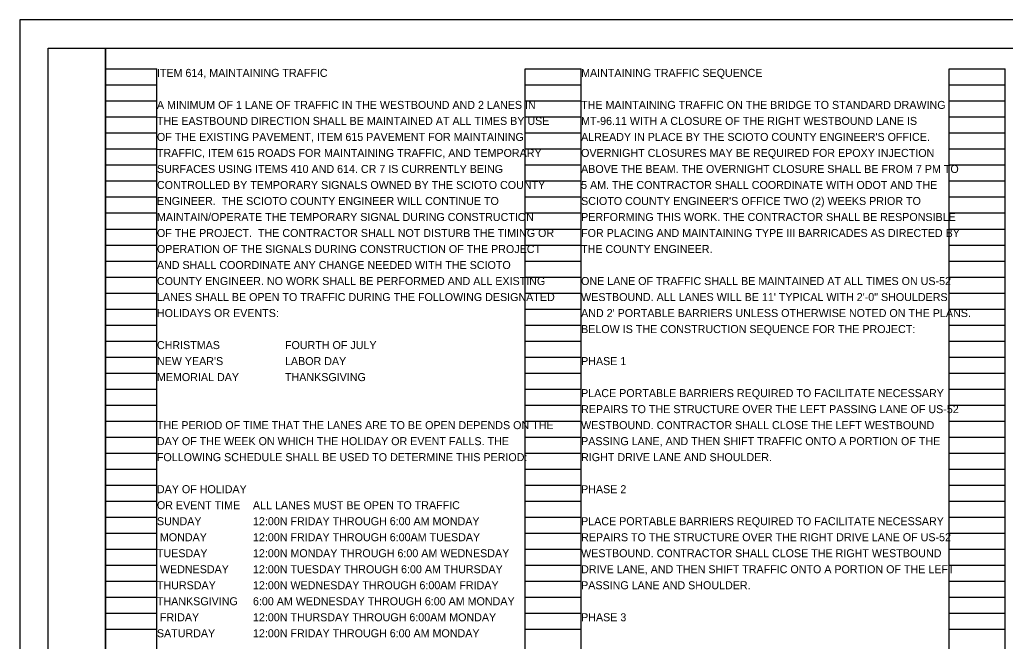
# Model space of a CAD drawing. Extents: x -36 to 68, y -39 to 86.
# Drawn here: x 0 to 17.24, y 11.13 to 22 of the extents above; entities that cross this region are included whole.
import ezdxf

# ---------------------------------------------------------------- set-up
doc = ezdxf.new("R2010")
doc.units = 0
for name, color, linetype in [('SH_Border', 7, 'Continuous'), ('SH_Cut_Line', 7, 'Continuous'), ('SH_Data', 7, 'Continuous'), ('SH_Text', 7, 'Continuous')]:
    doc.layers.add(name, color=color, linetype=linetype)

msp = doc.modelspace()

# ---------------------------------------------------------------- linework, layer by layer
at = {"layer": 'SH_Border'}
for points in [[(0.5, 21.5), (1.5, 21.5), (1.5, 0.5), (0.5, 0.5)], [(1.5, 21.5), (33.5, 21.5), (33.5, 0.5), (1.5, 0.5)]]:
    msp.add_lwpolyline(points, close=True, dxfattribs=at)
at = {"layer": 'SH_Cut_Line'}
msp.add_lwpolyline([(0, 0), (34, 0), (34, 22), (0, 22)], close=True, dxfattribs=at)
at = {"layer": 'SH_Data'}
for p, q in [((1.5, 0.98), (1.5, 21.14)), ((1.5, 21.14), (2.4, 21.14)), ((2.4, 0.98), (2.4, 21.14)), ((8.84, 0.98), (8.84, 21.14)), ((8.84, 21.14), (9.82, 21.14)), ((9.82, 0.98), (9.82, 21.14)), ((16.26, 0.98), (16.26, 21.14)), ((16.26, 21.14), (17.24, 21.14)), ((17.24, 0.98), (17.24, 21.14)), ((1.5, 20.86), (2.4, 20.86)), ((8.84, 20.86), (9.82, 20.86)), ((16.26, 20.86), (17.24, 20.86)), ((1.5, 20.58), (2.4, 20.58)), ((8.84, 20.58), (9.82, 20.58)), ((16.26, 20.58), (17.24, 20.58)), ((1.5, 20.3), (2.4, 20.3)), ((8.84, 20.3), (9.82, 20.3)), ((16.26, 20.3), (17.24, 20.3)), ((1.5, 20.02), (2.4, 20.02)), ((8.84, 20.02), (9.82, 20.02)), ((16.26, 20.02), (17.24, 20.02)), ((1.5, 19.74), (2.4, 19.74)), ((8.84, 19.74), (9.82, 19.74)), ((16.26, 19.74), (17.24, 19.74)), ((1.5, 19.46), (2.4, 19.46)), ((8.84, 19.46), (9.82, 19.46)), ((16.26, 19.46), (17.24, 19.46)), ((1.5, 19.18), (2.4, 19.18)), ((8.84, 19.18), (9.82, 19.18)), ((16.26, 19.18), (17.24, 19.18)), ((1.5, 18.9), (2.4, 18.9)), ((8.84, 18.9), (9.82, 18.9)), ((16.26, 18.9), (17.24, 18.9)), ((1.5, 18.62), (2.4, 18.62)), ((8.84, 18.62), (9.82, 18.62)), ((16.26, 18.62), (17.24, 18.62)), ((1.5, 18.34), (2.4, 18.34)), ((8.84, 18.34), (9.82, 18.34)), ((16.26, 18.34), (17.24, 18.34)), ((1.5, 18.06), (2.4, 18.06)), ((8.84, 18.06), (9.82, 18.06)), ((16.26, 18.06), (17.24, 18.06)), ((1.5, 17.78), (2.4, 17.78)), ((8.84, 17.78), (9.82, 17.78)), ((16.26, 17.78), (17.24, 17.78)), ((1.5, 17.5), (2.4, 17.5)), ((8.84, 17.5), (9.82, 17.5)), ((16.26, 17.5), (17.24, 17.5)), ((1.5, 17.22), (2.4, 17.22)), ((8.84, 17.22), (9.82, 17.22)), ((16.26, 17.22), (17.24, 17.22)), ((1.5, 16.94), (2.4, 16.94)), ((8.84, 16.94), (9.82, 16.94)), ((16.26, 16.94), (17.24, 16.94)), ((1.5, 16.66), (2.4, 16.66)), ((8.84, 16.66), (9.82, 16.66)), ((16.26, 16.66), (17.24, 16.66)), ((1.5, 16.38), (2.4, 16.38)), ((8.84, 16.38), (9.82, 16.38)), ((16.26, 16.38), (17.24, 16.38)), ((1.5, 16.1), (2.4, 16.1)), ((8.84, 16.1), (9.82, 16.1)), ((16.26, 16.1), (17.24, 16.1)), ((1.5, 15.82), (2.4, 15.82)), ((8.84, 15.82), (9.82, 15.82)), ((16.26, 15.82), (17.24, 15.82)), ((1.5, 15.54), (2.4, 15.54)), ((8.84, 15.54), (9.82, 15.54)), ((16.26, 15.54), (17.24, 15.54)), ((1.5, 15.26), (2.4, 15.26)), ((8.84, 15.26), (9.82, 15.26)), ((16.26, 15.26), (17.24, 15.26)), ((1.5, 14.98), (2.4, 14.98)), ((8.84, 14.98), (9.82, 14.98)), ((16.26, 14.98), (17.24, 14.98)), ((1.5, 14.7), (2.4, 14.7)), ((8.84, 14.7), (9.82, 14.7)), ((16.26, 14.7), (17.24, 14.7)), ((1.5, 14.42), (2.4, 14.42)), ((8.84, 14.42), (9.82, 14.42)), ((16.26, 14.42), (17.24, 14.42)), ((1.5, 14.14), (2.4, 14.14)), ((8.84, 14.14), (9.82, 14.14)), ((16.26, 14.14), (17.24, 14.14)), ((1.5, 13.86), (2.4, 13.86)), ((8.84, 13.86), (9.82, 13.86)), ((16.26, 13.86), (17.24, 13.86)), ((1.5, 13.58), (2.4, 13.58)), ((8.84, 13.58), (9.82, 13.58)), ((16.26, 13.58), (17.24, 13.58)), ((1.5, 13.3), (2.4, 13.3)), ((8.84, 13.3), (9.82, 13.3)), ((16.26, 13.3), (17.24, 13.3)), ((1.5, 13.02), (2.4, 13.02)), ((8.84, 13.02), (9.82, 13.02)), ((16.26, 13.02), (17.24, 13.02)), ((1.5, 12.74), (2.4, 12.74)), ((8.84, 12.74), (9.82, 12.74)), ((16.26, 12.74), (17.24, 12.74)), ((1.5, 12.46), (2.4, 12.46)), ((8.84, 12.46), (9.82, 12.46)), ((16.26, 12.46), (17.24, 12.46)), ((1.5, 12.18), (2.4, 12.18)), ((8.84, 12.18), (9.82, 12.18)), ((16.26, 12.18), (17.24, 12.18)), ((1.5, 11.9), (2.4, 11.9)), ((8.84, 11.9), (9.82, 11.9)), ((16.26, 11.9), (17.24, 11.9)), ((1.5, 11.62), (2.4, 11.62)), ((8.84, 11.62), (9.82, 11.62)), ((16.26, 11.62), (17.24, 11.62)), ((1.5, 11.34), (2.4, 11.34)), ((8.84, 11.34), (9.82, 11.34)), ((16.26, 11.34), (17.24, 11.34))]:
    msp.add_line(p, q, dxfattribs=at)

# ---------------------------------------------------------------- texts
at = {"layer": 'SH_Text'}
for s, p in [('ITEM 614, MAINTAINING TRAFFIC', (2.4, 21)), ('MAINTAINING TRAFFIC SEQUENCE', (9.82, 21)), ('A MINIMUM OF 1 LANE OF TRAFFIC IN THE WESTBOUND AND 2 LANES IN ', (2.4, 20.44)), ('THE MAINTAINING TRAFFIC ON THE BRIDGE TO STANDARD DRAWING ', (9.82, 20.44)), ('THE EASTBOUND DIRECTION SHALL BE MAINTAINED AT ALL TIMES BY USE ', (2.4, 20.16)), ('MT-96.11 WITH A CLOSURE OF THE RIGHT WESTBOUND LANE IS ', (9.82, 20.16)), ('OF THE EXISTING PAVEMENT, ITEM 615 PAVEMENT FOR MAINTAINING ', (2.4, 19.88)), ("ALREADY IN PLACE BY THE SCIOTO COUNTY ENGINEER'S OFFICE. ", (9.82, 19.88)), ('TRAFFIC, ITEM 615 ROADS FOR MAINTAINING TRAFFIC, AND TEMPORARY ', (2.4, 19.6)), ('OVERNIGHT CLOSURES MAY BE REQUIRED FOR EPOXY INJECTION ', (9.82, 19.6)), ('SURFACES USING ITEMS 410 AND 614. CR 7 IS CURRENTLY BEING ', (2.4, 19.32)), ('ABOVE THE BEAM. THE OVERNIGHT CLOSURE SHALL BE FROM 7 PM TO ', (9.82, 19.32)), ('CONTROLLED BY TEMPORARY SIGNALS OWNED BY THE SCIOTO COUNTY ', (2.4, 19.04)), ('5 AM. THE CONTRACTOR SHALL COORDINATE WITH ODOT AND THE ', (9.82, 19.04)), ('ENGINEER.  THE SCIOTO COUNTY ENGINEER WILL CONTINUE TO ', (2.4, 18.76)), ("SCIOTO COUNTY ENGINEER'S OFFICE TWO (2) WEEKS PRIOR TO ", (9.82, 18.76)), ('MAINTAIN/OPERATE THE TEMPORARY SIGNAL DURING CONSTRUCTION ', (2.4, 18.48)), ('PERFORMING THIS WORK. THE CONTRACTOR SHALL BE RESPONSIBLE ', (9.82, 18.48)), ('OF THE PROJECT.  THE CONTRACTOR SHALL NOT DISTURB THE TIMING OR ', (2.4, 18.2)), ('FOR PLACING AND MAINTAINING TYPE III BARRICADES AS DIRECTED BY ', (9.82, 18.2)), ('OPERATION OF THE SIGNALS DURING CONSTRUCTION OF THE PROJECT ', (2.4, 17.92)), ('THE COUNTY ENGINEER.', (9.82, 17.92)), ('AND SHALL COORDINATE ANY CHANGE NEEDED WITH THE SCIOTO ', (2.4, 17.64)), ('COUNTY ENGINEER. NO WORK SHALL BE PERFORMED AND ALL EXISTING ', (2.4, 17.36)), ('ONE LANE OF TRAFFIC SHALL BE MAINTAINED AT ALL TIMES ON US-52 ', (9.82, 17.36)), ('LANES SHALL BE OPEN TO TRAFFIC DURING THE FOLLOWING DESIGNATED ', (2.4, 17.08)), ('WESTBOUND. ALL LANES WILL BE 11\' TYPICAL WITH 2\'-0" SHOULDERS ', (9.82, 17.08)), ('HOLIDAYS OR EVENTS:', (2.4, 16.8)), ("AND 2' PORTABLE BARRIERS UNLESS OTHERWISE NOTED ON THE PLANS. ", (9.82, 16.8)), ('BELOW IS THE CONSTRUCTION SEQUENCE FOR THE PROJECT:', (9.82, 16.52)), ('CHRISTMAS', (2.4, 16.24)), ('FOURTH OF JULY', (4.64, 16.24)), ("NEW YEAR'S", (2.4, 15.96)), ('LABOR DAY', (4.64, 15.96)), ('PHASE 1', (9.82, 15.96)), ('MEMORIAL DAY', (2.4, 15.68)), ('THANKSGIVING', (4.64, 15.68)), ('PLACE PORTABLE BARRIERS REQUIRED TO FACILITATE NECESSARY ', (9.82, 15.4)), ('REPAIRS TO THE STRUCTURE OVER THE LEFT PASSING LANE OF US-52 ', (9.82, 15.12)), ('THE PERIOD OF TIME THAT THE LANES ARE TO BE OPEN DEPENDS ON THE ', (2.4, 14.84)), ('WESTBOUND. CONTRACTOR SHALL CLOSE THE LEFT WESTBOUND ', (9.82, 14.84)), ('DAY OF THE WEEK ON WHICH THE HOLIDAY OR EVENT FALLS. THE ', (2.4, 14.56)), ('PASSING LANE, AND THEN SHIFT TRAFFIC ONTO A PORTION OF THE ', (9.82, 14.56)), ('FOLLOWING SCHEDULE SHALL BE USED TO DETERMINE THIS PERIOD:', (2.4, 14.28)), ('RIGHT DRIVE LANE AND SHOULDER.', (9.82, 14.28)), ('DAY OF HOLIDAY', (2.4, 13.72)), ('PHASE 2', (9.82, 13.72)), ('OR EVENT TIME', (2.4, 13.44)), ('ALL LANES MUST BE OPEN TO TRAFFIC', (4.08, 13.44)), ('SUNDAY', (2.4, 13.16)), ('12:00N FRIDAY THROUGH 6:00 AM MONDAY', (4.08, 13.16)), ('PLACE PORTABLE BARRIERS REQUIRED TO FACILITATE NECESSARY ', (9.82, 13.16)), (' MONDAY', (2.4, 12.88)), ('12:00N FRIDAY THROUGH 6:00AM TUESDAY', (4.08, 12.88)), ('REPAIRS TO THE STRUCTURE OVER THE RIGHT DRIVE LANE OF US-52 ', (9.82, 12.88)), ('TUESDAY', (2.4, 12.6)), ('12:00N MONDAY THROUGH 6:00 AM WEDNESDAY', (4.08, 12.6)), ('WESTBOUND. CONTRACTOR SHALL CLOSE THE RIGHT WESTBOUND ', (9.82, 12.6)), (' WEDNESDAY', (2.4, 12.32)), ('12:00N TUESDAY THROUGH 6:00 AM THURSDAY', (4.08, 12.32)), ('DRIVE LANE, AND THEN SHIFT TRAFFIC ONTO A PORTION OF THE LEFT ', (9.82, 12.32)), ('THURSDAY', (2.4, 12.04)), ('12:00N WEDNESDAY THROUGH 6:00AM FRIDAY', (4.08, 12.04)), ('PASSING LANE AND SHOULDER.', (9.82, 12.04)), ('THANKSGIVING', (2.4, 11.76)), ('6:00 AM WEDNESDAY THROUGH 6:00 AM MONDAY', (4.08, 11.76)), (' FRIDAY', (2.4, 11.48)), ('12:00N THURSDAY THROUGH 6:00AM MONDAY', (4.08, 11.48)), ('PHASE 3', (9.82, 11.48)), ('SATURDAY', (2.4, 11.2)), ('12:00N FRIDAY THROUGH 6:00 AM MONDAY', (4.08, 11.2))]:
    msp.add_text(s, height=0.14, dxfattribs=at).set_placement(p)

doc.saveas('drawing.dxf')
